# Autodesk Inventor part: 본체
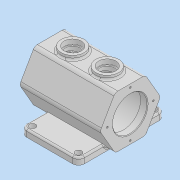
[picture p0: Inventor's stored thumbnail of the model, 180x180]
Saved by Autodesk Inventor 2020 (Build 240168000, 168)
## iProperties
Created: 2021-06
Part Number: 본체
Material: 일반
Document SubType Name: Modeling
Designer: MIRAE
Density: 1 g/cm^3
Appearance: 기본값
Mass: 557.084 g
Surface Area: 1100.31 cm^2
Volume: 557.084 cm^3
Author: MIRAE
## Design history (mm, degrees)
sketch "스케치1"
  geometry: L1 (-50, -75)-(50, -75); L2 (50, -75)-(50, 75); L3 (50, 75)-(-50, 75); L4 (-50, 75)-(-50, -75); L5 (-50, -75)-(50, 75); L6 (50, -75)-(-50, 75); 1 further point
  constraints: 12 end point, 2 midpoint, 2 parallel, 1 horizontal, 1 perpendicular
  dimensions: "d0" = 100 distance of L3.end L2.end; "d1" = 150 distance of L2.end L1.end
extrude "돌출1" new body sketch "스케치1" distance "d2" = 12; taper "d3" = 0 deg
sketch "스케치13"
  geometry: L1 (-52.5, 50)-(-26.25, 95.466); L2 (-26.25, 95.466)-(26.25, 95.466); L3 (26.25, 95.466)-(52.5, 50); L4 (52.5, 50)-(26.25, 4.534); L5 (26.25, 4.534)-(-26.25, 4.534); L6 (-26.25, 4.534)-(-52.5, 50); L7 (75, 0)-(-75, 0) reference; 4 further points
  constraints: 12 end point, 2 midpoint, 1 parallel, 1 vertical alignment, 13 other
  dimensions: "d64" = 105 distance of L3.end L1.start; "d65" = 50 distance from line of L7 point (0, 50)
extrude "돌출5" join sketch "스케치13" distance "d66" = 65; taper "d67" = 0 deg
sketch "스케치14"
  geometry: L1 (50, -52.5)-(12, -30.561) reference; L2 (95.466, -26.25)-(50, -52.5) reference; L3 (95.466, 26.25)-(95.466, -26.25) reference; L4 (50, 52.5)-(95.466, 26.25) reference; L5 (12, 30.561)-(50, 52.5) reference; L6 (50, -52.5)-(4.534, -26.25); L7 (4.534, -26.25)-(4.534, 26.25); L8 (4.534, 26.25)-(50, 52.5); L9 (50, 52.5)-(95.466, 26.25); L10 (95.466, 26.25)-(95.466, -26.25); L11 (95.466, -26.25)-(50, -52.5); 4 further points
  constraints: 12 end point, 13 other
extrude "돌출6" join sketch "스케치14" distance "d68" = 75; taper "d69" = 0 deg
sketch "스케치15"
  geometry: L1 (75, 50)-(-65, 50) reference; L2 (0, 50)-(-53, 50); L3 (-53, 50)-(-53, 87.5); L4 (-53, 87.5)-(0, 87.5); L5 (0, 87.5)-(0, 50); L6 (-53, 50)-(-65, 50); L7 (-65, 50)-(-65, 80); L8 (-65, 80)-(-53, 80); L9 (-53, 80)-(-53, 50); L10 (0, 50)-(63, 50); L11 (63, 50)-(63, 87.5); L12 (63, 87.5)-(0, 87.5); L13 (0, 87.5)-(0, 50); L14 (75, 95.466)-(75, 50) reference; L15 (63, 80)-(75, 80); L16 (75, 80)-(75, 50); L17 (75, 50)-(63, 50); L18 (63, 50)-(63, 80); L19 (-65, 4.534)-(-65, 50) reference; 6 further points
  constraints: 32 end point, 8 parallel, 4 horizontal, 4 perpendicular, 3 point on line, 1 collinear, 1 midpoint, 1 vertical alignment
  dimensions: "d70" = 12 distance of L15.start L15.end; "d71" = 12 distance of L7.end L8.end; "d72" = 60 diameter of L15 L1; "d73" = 75 diameter of L12 L1; "d74" = 60 diameter of L8 L2
revolve "회전2" sketch "스케치15" stored, may be unused: angle "d75" = 90 deg
node "작업 평면2"
sketch "스케치16"
  geometry: L1 (-75, -26.25)-(-75, 26.25) reference; C1 r 20 at (-35, 0); C2 r 20 at (25, 0); 1 further point
  constraints: 2 centre point, 2 horizontal alignment
  dimensions: "d77" = 40 distance from line of C1.centre L1; "d78" = 60 distance of C2.centre C1.centre; "d79" = 40 diameter of C1; "d80" = 40 diameter of C2
extrude "돌출7" join sketch "스케치16" stored distance "d81" = 75; taper "d82" = 0 deg
sketch "스케치18"
  geometry: C1 r 20 at (0, 0) reference; C2 r 20 at (60, 0) reference; 3 further points
  constraints: 2 coincident
hole "구멍4" sketch "스케치18" at (0, 0), (60, 0) diameter "d83" = 25; stored, may be unused: countersink angle "d87" = 90 deg, drill point angle "d89" = 118 deg; dims "d84" = 8, "d85" = 30, "d86" = 8, "d88" = 10
sketch "스케치19" dims "d91" = 80
  geometry: L1 (-50, 0)-(-50, -52.5); L2 (-50, 0)-(-121.036, 0); C1 r 30 at (-50, 0) reference; 3 further points
  constraints: 4 end point, 1 coincident, 1 horizontal alignment, 1 point on line, 2 other
  dimensions: "d90" = 90 deg angle of L1 L2
hole "구멍5" sketch "스케치19" at (-90, 0) diameter "d92" = 3.242; stored, may be unused: countersink angle "d96" = 90 deg, drill point angle "d98" = 118 deg; dims "d93" = 8, "d94" = 30, "d95" = 8, "d97" = 10
sketch "스케치20" dims "d133" = 80
  geometry: L1 (50, 0)-(50, 52.5); L2 (50, 0)-(92.934, 42.934); C1 r 30 at (50, 0) reference; 3 further points
  constraints: 4 end point, 1 coincident, 1 point on line, 1 vertical, 3 other
  dimensions: "d132" = 45 deg angle of L1 L2
hole "구멍6" sketch "스케치20" at (78.284, 28.284) diameter "d104" = 3.242; stored, may be unused: countersink angle "d108" = 90 deg, drill point angle "d110" = 118 deg; dims "d105" = 8, "d106" = 30, "d107" = 8, "d109" = 10
fillet "모깎기3" dims "d114" = 10, "d115" = 8, "d116" = 5
fillet "모깎기4" dims "d117" = 3
chamfer "모따기2" distance "d118" = 1; stored, may be unused: second distance "d119" = 2, angle "d120" = 45 deg
sketch "스케치21"
  geometry: A1 r 7 centre (-40, -65) between (-47, -65) and (-40, -72) reference; A2 r 7 centre (40, -65) between (40, -72) and (47, -65) reference; A3 r 10 centre (-40, 65) between (-40, 75) and (-50, 65) reference; A4 r 10 centre (40, 65) between (50, 65) and (40, 75) reference; 1 further point
hole "구멍7" sketch "스케치21" at (-40, 65), (40, 65), (-40, -65), (40, -65) diameter "d121" = 11; stored, may be unused: countersink angle "d125" = 90 deg, drill point angle "d127" = 118 deg; dims "d122" = 8, "d123" = 30, "d124" = 8, "d126" = 10
sketch "스케치22"
  geometry: L1 (40, 75)-(-40, 75) reference; L2 (-50, 65)-(-50, 32.293) reference; 2 further points
  constraints: 1 other
  dimensions: "d128" = 14 distance from line of L1 point (0, 61); "d129" = 50 distance from line of point (0, 61) L2
feature "엠보싱2" sketch "스케치22" dims "d130" = 0.5, "d131" = 0
sketch "스케치23"
  geometry: L1 (-124.018, 0)-(-124.018, -91.641); L2 (-124.018, -91.641)-(21.616, -91.641); L3 (21.616, -91.641)-(21.616, 0); L4 (-124.018, 0)-(21.616, 0)
  constraints: 8 end point, 1 horizontal, 1 parallel
extrude "돌출8" cut sketch "스케치23" extent not by distance; stored distance "d137" = 0; taper "d138" = 0 deg
node "솔리드1"
pattern_circular "원형 패턴3" dims angle "d112" = 360 deg
pattern_circular "원형 패턴4" dims angle "d135" = 360 deg
feature "A9D066F2-1C7D-4E18-AEED-F7BC21143FA4" dims "d92" = 3.242, "d93" = 8, "d94" = 30, "d95" = 8, "d96" = 90 deg, "d97" = 10, "d98" = 118 deg
other parameters: "d76" = 102.5
